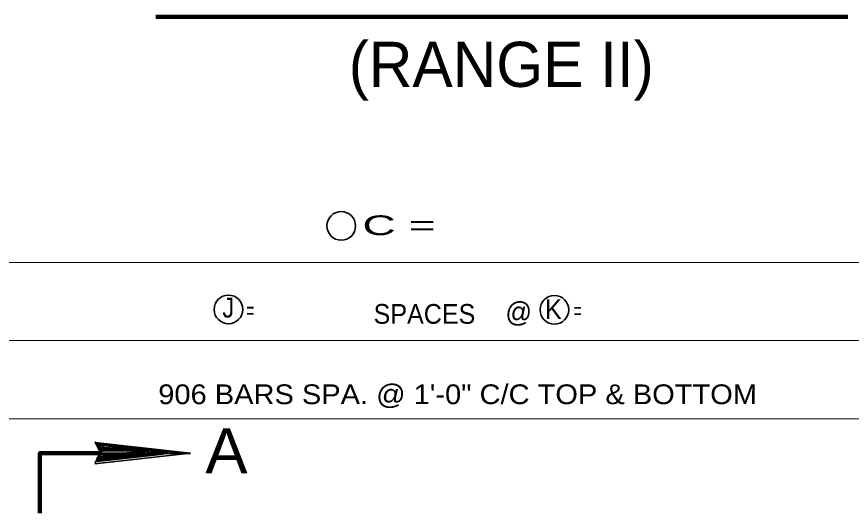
# Model space of a CAD drawing. Extents: x 144 to 252, y 360 to 425.
# Drawn here: x 160.9 to 174.77, y 380.09 to 388.34 of the extents above; entities that cross this region are included whole.
import ezdxf
from ezdxf.enums import TextEntityAlignment as Align

# ---------------------------------------------------------------- set-up
doc = ezdxf.new("R2010")
doc.units = 0
doc.header["$LTSCALE"] = 0.13
for name, color, linetype, lineweight in [('1', 7, 'Continuous', 40), ('14', 7, 'Continuous', 13), ('16', 7, 'Continuous', 13), ('3', 7, 'Continuous', 13)]:
    doc.layers.add(name, color=color, linetype=linetype, lineweight=lineweight)

msp = doc.modelspace()

# ---------------------------------------------------------------- linework, layer by layer
at = {"layer": '1', "lineweight": 13}
msp.add_line((177.4166, 381.6627), (157.3739, 381.6627), dxfattribs=at)
at = {"layer": '1', "lineweight": 35}
for p, q in [((162.1968, 381.2682), (163.7868, 381.0913)), ((162.2358, 381.2532), (163.4208, 381.1242)), ((162.2388, 381.2593), (163.4208, 381.1302)), ((162.2298, 381.0043), (163.3338, 381.1242)), ((162.2328, 381.2262), (163.4148, 381.0972)), ((162.2358, 381.2473), (163.4208, 381.1212)), ((162.2358, 381.2412), (163.4148, 381.1092)), ((163.7898, 381.0882), (162.1998, 380.9112)), ((162.1998, 381.0852), (163.7898, 381.0852)), ((162.2328, 380.9862), (163.3338, 381.1062)), ((162.2358, 380.9683), (163.3398, 381.0882)), ((162.2388, 380.9532), (163.3428, 381.0732))]:
    msp.add_line(p, q, dxfattribs=at)
for points in [[(162.2028, 380.9262), (162.2868, 381.1062), (162.2028, 381.2802)], [(162.3108, 381.1242), (163.0188, 381.1332), (163.0158, 381.1153), (162.8778, 381.1242), (162.3108, 381.1332), (162.7668, 381.1482), (162.2898, 381.1572), (162.6258, 381.1692), (162.2778, 381.1873), (162.8208, 381.1452), (163.5288, 381.1153), (163.3818, 381.0762), (163.5768, 381.0942), (162.3108, 381.0882), (162.6798, 381.0643), (162.2898, 381.0643), (163.0998, 381.1212), (162.2838, 381.0312), (162.3138, 381.1212), (162.2478, 381.2322), (162.2838, 381.2082), (162.3138, 381.1452), (162.3558, 381.1633), (162.3288, 381.2142), (162.3048, 381.1002), (162.2718, 381.0312), (162.2388, 380.9532)]]:
    msp.add_lwpolyline(points, dxfattribs=at)
for centre in [(166.2952, 384.8668), (164.4208, 383.4781), (169.8383, 383.4714)]:
    msp.add_circle(centre, 0.238, dxfattribs=at)
at = {"layer": '14', "lineweight": 106}
msp.add_line((163.2148, 388.3425), (174.7148, 388.3425), dxfattribs=at)
at = {"layer": '16', "lineweight": 106}
msp.add_lwpolyline([(161.2877, 380.0908), (161.2877, 381.0908), (162.2877, 381.0908)], dxfattribs=at)
at = {"layer": '3'}
for p, q in [((156.3791, 384.2597), (180.3798, 384.2597)), ((156.38, 382.9646), (179.0847, 382.9646))]:
    msp.add_line(p, q, dxfattribs=at)

# ---------------------------------------------------------------- texts
at = {"layer": '1'}
for s, height, width, p in [('J', 0.3281, 0.9, (164.4183, 383.3434)), ('K', 0.3281, 0.95, (169.8233, 383.3173)), ('=', 0.2833, 0.6, (164.7863, 383.3207)), ('=', 0.2833, 0.6, (170.2252, 383.3171))]:
    msp.add_text(s, height=height, dxfattribs=dict(at, width=width)).set_placement(p, align=Align.CENTER)
msp.add_text('@', height=0.3281, dxfattribs=at).set_placement((169.2456, 383.2724), align=Align.CENTER)
at = {"layer": '1', "width": 0.95}
msp.add_text('SPACES', height=0.3281, dxfattribs=at).set_placement((166.8335, 383.2398))
at = {"layer": '14'}
msp.add_text('(RANGE II)', height=0.75, dxfattribs=at).set_placement((168.9562, 387.1757), align=Align.CENTER)
at = {"layer": '16', "width": 1.75}
msp.add_text('C =      ', height=0.3281, dxfattribs=at).set_placement((167.8953, 384.7128), align=Align.CENTER)
at = {"layer": '16'}
for s, height, width, p in [('906 BARS SPA. @ 1\'-0" C/C TOP & BOTTOM', 0.3281, 1.1, (163.254, 381.9045)), ('A', 0.75, 1.05, (164.0358, 380.7546))]:
    msp.add_text(s, height=height, dxfattribs=dict(at, width=width)).set_placement(p)

doc.saveas('drawing.dxf')
